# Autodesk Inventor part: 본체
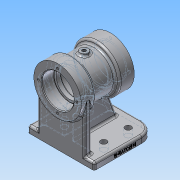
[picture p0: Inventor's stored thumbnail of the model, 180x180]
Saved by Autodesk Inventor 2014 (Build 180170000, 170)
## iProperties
Created: 2020-06
Part Number: 본체
Material: 알루미늄 6061
Document SubType Name: Modeling
Designer: net
Density: 2.71 g/cm^3
Appearance: 알루미늄 - 평지
Author: net
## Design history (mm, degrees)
sketch "스케치1"
  geometry: L1 (39, 0)-(-39, 0); L2 (39, 0)-(39, 35); L3 (39, 35)-(17, 35); L4 (17, 35)-(17, 29); L5 (17, 29)-(-17, 29); L6 (-17, 29)-(-17, 35); L7 (-17, 35)-(-39, 35); L8 (-39, 35)-(-39, 0); 2 further points
  constraints: 16 end point, 4 parallel, 2 collinear, 2 perpendicular, 1 coincident, 1 horizontal, 1 midpoint
  dimensions: "d0" = 78 distance of L1.start L1.end; "d1" = 22 distance of L2.end L3.end; "d2" = 22 distance of L6.end L7.end; "d3" = 70 diameter of L3 L1; "d4" = 58 diameter of L5 L1
revolve "회전1" sketch "스케치1" stored, may be unused: angle "d5" = 90 deg
sketch "스케치2"
  geometry: C1 r 35 at (0, 0) reference; C2 r 23.5 at (0, 0)
  constraints: 1 centre point, 1 coincident
  dimensions: "d6" = 47 diameter of C2
extrude "돌출1" cut sketch "스케치2" distance "d7" = 18; taper "d8" = 0 deg
sketch "스케치3"
  geometry: C1 r 23 at (0, 0); 1 further point
  constraints: 1 centre point, 1 coincident
  dimensions: "d9" = 46 diameter of C1
extrude "돌출2" cut sketch "스케치3" stored distance "d10" = 30; taper "d11" = 0 deg
fillet "모깎기1" dims "d12" = 0.3
fillet "모깎기2" dims "d13" = 3
sketch "스케치4"
  geometry: C1 r 23.2 at (0, 0) reference; C2 r 20 at (0, 0)
  constraints: 1 centre point, 1 coincident
  dimensions: "d14" = 40 diameter of C2
extrude "돌출3" cut sketch "스케치4" stored distance "d15" = 30; taper "d16" = 0 deg
chamfer "모따기1" distance "d17" = 1; stored, may be unused: second distance "d18" = 2, angle "d19" = 45 deg
sketch "스케치5" dims "d20" = 57
  geometry: C1 r 35 at (0, 0) reference; C2 r 24.5 at (0, 0) reference; 2 further points
  constraints: 2 vertical alignment, 1 coincident, 2 other
hole "구멍1" sketch "스케치5" at (0, 28.5) diameter "d21" = 3.242; stored, may be unused: countersink angle "d25" = 90 deg, drill point angle "d27" = 118 deg; dims "d22" = 10, "d23" = 4, "d24" = 2, "d26" = 12
node "작업 평면2"
sketch "스케치7"
  geometry: C1 r 6 at (0, 0); 1 further point
  constraints: 1 centre point, 1 coincident
  dimensions: "d34" = 12 diameter of C1
extrude "돌출4" join sketch "스케치7" stored distance "d35" = 30; taper "d36" = 0 deg
hole "구멍2" diameter "d39" = 5.188; stored, may be unused: countersink angle "d43" = 90 deg, drill point angle "d45" = 118 deg; dims "d37" = 10, "d38" = 10, "d40" = 10, "d41" = 4, "d42" = 2, "d44" = 12
fillet "모깎기3" dims "d46" = 3
node "작업 평면4"
sketch "스케치8"
  geometry: L1 (-39, 35)-(-39, -35) reference; L2 (-34, 49)-(56, 49); L3 (56, 49)-(56, -49); L4 (56, -49)-(-34, -49); L5 (-34, -49)-(-34, 49); 3 further points
  constraints: 8 end point, 2 midpoint, 2 parallel, 1 horizontal, 1 horizontal alignment, 1 perpendicular
  dimensions: "d49" = 90 distance of L2.start L2.end; "d50" = 98 distance of L2.end L3.end; "d51" = 5 distance between parallel lines of L5 L1
extrude "돌출5" join sketch "스케치8" distance "d52" = 10; taper "d53" = 0 deg
sketch "스케치9"
  geometry: L1 (-34, 49)-(-34, -49) reference; L2 (-34, 35)-(-24, 35); L3 (-24, 35)-(-24, -35); L4 (-24, -35)-(-34, -35); L5 (-34, -35)-(-34, 35); 3 further points
  constraints: 8 end point, 3 midpoint, 2 parallel, 1 coincident, 1 horizontal, 1 perpendicular
  dimensions: "d54" = 70 distance of L4.end L2.start; "d55" = 10 distance of L2.start L2.end
extrude "돌출6" join sketch "스케치9" stored distance "d56" = 10; taper "d57" = 0 deg
sketch "스케치10"
  geometry: L1 (21, 20)-(15, 20) reference; L2 (12, 23)-(2.594, 23) reference; L3 (2.594, 23)-(2.594, 32) reference; L4 (2.594, 32)-(6, 32) reference; L5 (9, 29)-(14, 29) reference; L6 (20, 35)-(39, 35) reference; L7 (39, 35)-(39, 30.121) reference; L8 (39, 30.121)-(27, 30.121) reference; L9 (27, 30.121)-(26.026, 28.5) reference; L10 (26.026, 28.5)-(27, 26.879) reference; L11 (27, 26.879)-(39, 26.879) reference; L12 (39, 26.879)-(39, 24.5) reference; L13 (39, 24.5)-(38, 23.5) reference; L14 (38, 23.5)-(21.3, 23.5) reference; L15 (21, 23.2)-(21, 20) reference; L16 (-15, 20)-(-21, 20) reference; L17 (-21, 20)-(-21, 23.2) reference; L18 (-21.3, 23.5)-(-38, 23.5) reference; L19 (-38, 23.5)-(-39, 24.5) reference; L20 (-39, 24.5)-(-39, 26.879) reference; L21 (-39, 26.879)-(-27, 26.879) reference; L22 (-27, 26.879)-(-26.026, 28.5) reference; L23 (-26.026, 28.5)-(-27, 30.121) reference; L24 (-27, 30.121)-(-39, 30.121) reference; L25 (-39, 30.121)-(-39, 35) reference; L26 (-39, 35)-(-20, 35) reference; L27 (-14, 29)-(-9, 29) reference; L28 (-6, 32)-(-2.594, 32) reference; L29 (-2.594, 32)-(-2.594, 23) reference; L30 (-2.594, 23)-(-12, 23) reference; L31 (-21, -20)-(-15, -20) reference; L32 (-12, -23)-(12, -23) reference; L33 (15, -20)-(21, -20) reference; L34 (21, -20)-(21, -23.2) reference; L35 (21.3, -23.5)-(38, -23.5) reference; L36 (38, -23.5)-(39, -24.5) reference; L37 (39, -24.5)-(39, -26.879) reference; L38 (39, -26.879)-(27, -26.879) reference; L39 (27, -26.879)-(26.026, -28.5) reference; L40 (26.026, -28.5)-(27, -30.121) reference; L41 (27, -30.121)-(39, -30.121) reference; L42 (39, -30.121)-(39, -35) reference; L43 (39, -35)-(34, -35) reference; L44 (34, -35)-(34, -80) reference; L45 (34, -80)-(-56, -80) reference; L46 (-56, -80)-(-56, -70) reference; L47 (-56, -70)-(24, -70) reference; L48 (24, -70)-(24, -35) reference; L49 (24, -35)-(20, -35) reference; L50 (14, -29)-(-14, -29) reference; L51 (-20, -35)-(-39, -35) reference; L52 (-39, -35)-(-39, -30.121) reference; L53 (-39, -30.121)-(-27, -30.121) reference; L54 (-27, -30.121)-(-26.026, -28.5) reference; L55 (-26.026, -28.5)-(-27, -26.879) reference; L56 (-27, -26.879)-(-39, -26.879) reference; L57 (-39, -26.879)-(-39, -24.5) reference; L58 (-39, -24.5)-(-38, -23.5) reference; L59 (-38, -23.5)-(-21.3, -23.5) reference; L60 (-21, -23.2)-(-21, -20) reference; L61 (-44, -70)-(-31.261, -35); A1 r 3 centre (12, 20) between (15, 20) and (12, 23) reference; A2 r 3 centre (14, 32) between (14, 29) and (17, 32) reference; A3 r 3 centre (20, 32) between (20, 35) and (17, 32) reference; A4 r 0.3 centre (21.3, 23.2) between (21.3, 23.5) and (21, 23.2) reference; A5 r 0.3 centre (-21.3, 23.2) between (-21, 23.2) and (-21.3, 23.5) reference; A6 r 3 centre (-20, 32) between (-17, 32) and (-20, 35) reference; A7 r 3 centre (-14, 32) between (-17, 32) and (-14, 29) reference; A8 r 3 centre (-12, 20) between (-12, 23) and (-15, 20) reference; A9 r 3 centre (-12, -20) between (-15, -20) and (-12, -23) reference; A10 r 3 centre (12, -20) between (12, -23) and (15, -20) reference; A11 r 0.3 centre (21.3, -23.2) between (21, -23.2) and (21.3, -23.5) reference; A12 r 3 centre (20, -32) between (17, -32) and (20, -35) reference; A13 r 3 centre (14, -32) between (17, -32) and (14, -29) reference; A14 r 3 centre (-14, -32) between (-14, -29) and (-17, -32) reference; A15 r 3 centre (-20, -32) between (-20, -35) and (-17, -32) reference; A16 r 0.3 centre (-21.3, -23.2) between (-21.3, -23.5) and (-21, -23.2) reference; 1 further point
  constraints: 2 end point, 2 point on line, 2 other
  dimensions: "d58" = 12 horizontal distance of L45.end L61.start; "d59" = 70 deg angle of L61 L47
feature "리브1" sketch "스케치10" dims "d60" = 1, "d61" = 10, "d62" = 0, "d63" = 0, "d64" = 1, "d65" = 1
fillet "모깎기4" dims "d66" = 20
fillet "모깎기5" dims "d67" = 3
fillet "모깎기6" dims "d68" = 3
fillet "모깎기7" dims "d69" = 3
fillet "모깎기8" dims "d70" = 3
fillet "모깎기9" dims "d71" = 3
fillet "모깎기10" dims "d72" = 3
sketch "스케치11"
  geometry: A1 r 17 centre (36, -29) between (36, -46) and (53, -29) reference; A2 r 17 centre (36, 29) between (53, 29) and (36, 46) reference; 5 further points
  constraints: 2 coincident, 2 horizontal alignment, 1 vertical alignment
  dimensions: "d73" = 36 distance of point (36, 29) point (0, 29); "d74" = 58 distance of point (36, -29) point (36, 29) (derived)
hole "구멍3" sketch "스케치11" at (36, 29), (0, 29), (36, -29), (0, -29) diameter "d75" = 9; stored, may be unused: countersink angle "d79" = 90 deg, drill point angle "d81" = 118 deg; dims "d76" = 10, "d77" = 4, "d78" = 2, "d80" = 12
sketch "스케치12"
  geometry: L1 (67, 0)-(0, 0) reference; L2 (-3, 7)-(-3, 0) reference; 2 further points
  constraints: 1 other
  dimensions: "d82" = 4 distance from line of point (42, 4) L1; "d83" = 45 distance from line of point (42, 4) L2
feature "엠보싱1" sketch "스케치12" dims "d9" = 46, "d84" = 0.5, "d85" = 0
node "솔리드1"
mirror "대칭1"
pattern_circular "원형 패턴1" dims angle "d29" = 360 deg
mirror "대칭2"
node "절단 모서리 투영1"
other parameters: "d33" = 32
